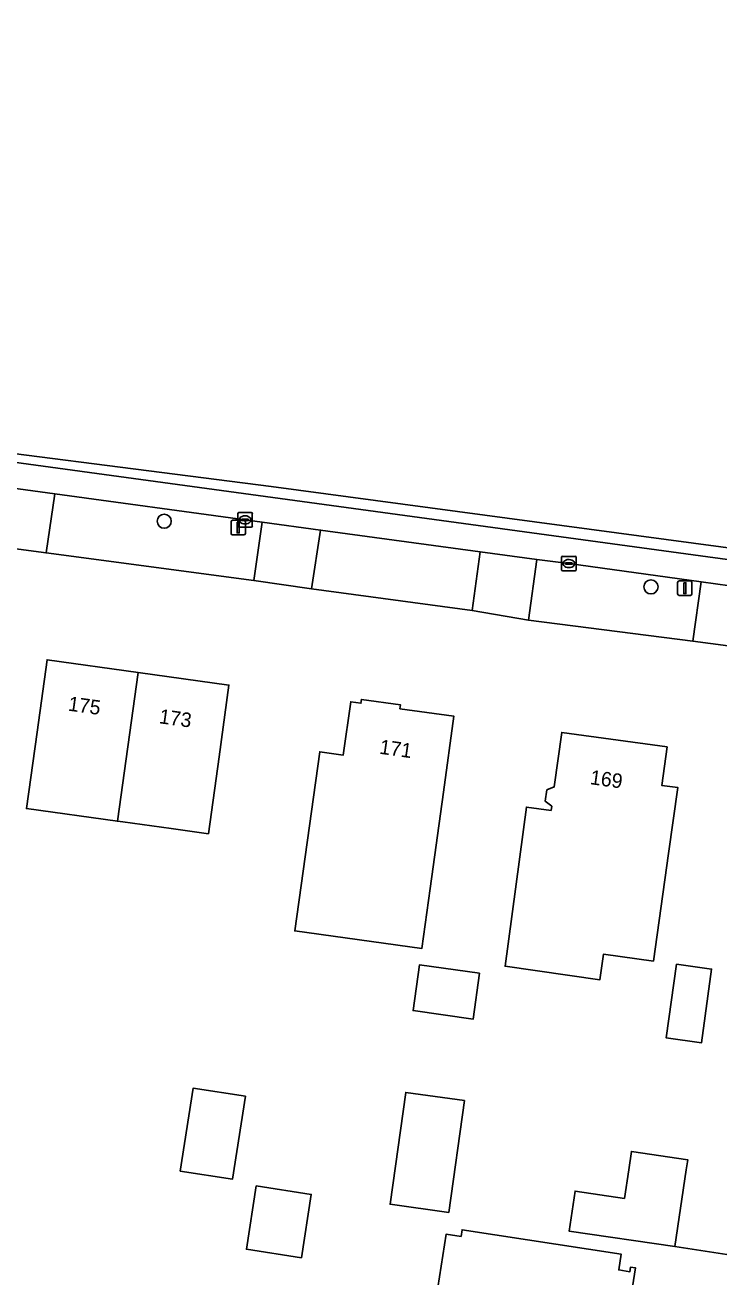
# Model space of a CAD drawing. Extents: x 161483 to 162250, y 379484 to 380833.
# Drawn here: x 161897.6 to 161945.6, y 380742.6 to 380829.1 of the extents above; entities that cross this region are included whole.
import ezdxf

# ---------------------------------------------------------------- set-up
doc = ezdxf.new("R2010")
doc.units = 0
for name, color, linetype in [('IMGEO_Boom', 7, 'Continuous'), ('IMGEO_Erf', 7, 'Continuous'), ('IMGEO_Fietspad_open', 7, 'Continuous'), ('IMGEO_Kolk', 7, 'Continuous'), ('IMGEO_Lichtmast', 7, 'Continuous'), ('IMGEO_Muur', 7, 'Continuous'), ('IMGEO_Pand', 7, 'Continuous'), ('IMGEO_Pand_nummerreeks', 7, 'Continuous'), ('IMGEO_Rijbaan_lokaal_gesloten', 7, 'Continuous'), ('IMGEO_Voetpad_open', 7, 'Continuous')]:
    doc.layers.add(name, color=color, linetype=linetype)

msp = doc.modelspace()

# ---------------------------------------------------------------- linework, layer by layer
at = {"layer": 'IMGEO_Boom'}
for centre in [(161907.254, 380794.81), (161940.876, 380790.272)]:
    msp.add_circle(centre, 0.489, dxfattribs=at)
at = {"layer": 'IMGEO_Erf'}
for points in [[(161947.776, 380785.993), (161943.772, 380786.523), (161932.427, 380787.968), (161928.533, 380788.644), (161917.439, 380790.128), (161913.448, 380790.714), (161899.09, 380792.619), (161891.993, 380793.568), (161881.272, 380795.068), (161877.324, 380795.561), (161866.903, 380796.964), (161862.786, 380797.518), (161845.524, 380799.914), (161837.657, 380800.986)], [(161926.166, 380741.862), (161926.734, 380745.548), (161927.761, 380745.389), (161927.832, 380745.853), (161938.822, 380744.157), (161938.654, 380743.069), (161939.424, 380742.95), (161939.474, 380743.275), (161939.8, 380743.225), (161938.78, 380736.645)]]:
    msp.add_lwpolyline(points, dxfattribs=at)
for points in [[(161911.042, 380778.536), (161910.304, 380773.211), (161907.742, 380773.567), (161904.397, 380774.032), (161904.022, 380774.075), (161897.735, 380774.947), (161898.469, 380780.238), (161899.161, 380785.231), (161905.445, 380784.36), (161911.729, 380783.488)], [(161916.273, 380766.5), (161917.998, 380778.875), (161919.624, 380778.649), (161920.136, 380782.334), (161920.845, 380782.235), (161920.881, 380782.495), (161923.58, 380782.12), (161923.542, 380781.847), (161927.268, 380781.33), (161926.551, 380776.089), (161925.626, 380769.427), (161925.049, 380765.276)], [(161932.274, 380775.058), (161933.984, 380774.825), (161934.024, 380775.116), (161933.578, 380775.464), (161933.686, 380776.244), (161934.198, 380776.452), (161934.72, 380780.218), (161941.991, 380779.21), (161941.62, 380776.554), (161942.727, 380776.412), (161942.091, 380771.854), (161941.053, 380764.418), (161937.601, 380764.9), (161937.349, 380763.122), (161930.801, 380764.057)], [(161929.043, 380763.574), (161928.602, 380760.409), (161924.445, 380760.989), (161924.886, 380764.154)], [(161942.64, 380764.197), (161945.061, 380763.861), (161944.378, 380758.777), (161941.931, 380759.11)], [(161912.863, 380755.076), (161911.972, 380749.338), (161908.367, 380749.898), (161909.258, 380755.636)], [(161927.99, 380754.774), (161926.912, 380747.045), (161922.861, 380747.61), (161923.939, 380755.339)], [(161939.527, 380751.264), (161943.416, 380750.69), (161943.314, 380750), (161942.53, 380744.682), (161935.226, 380745.759), (161935.633, 380748.522), (161939.048, 380748.017), (161939.341, 380750)], [(161917.415, 380748.294), (161916.735, 380743.917), (161912.936, 380744.507), (161913.616, 380748.884)]]:
    msp.add_lwpolyline(points, close=True, dxfattribs=at)
at = {"layer": 'IMGEO_Fietspad_open'}
for points in [[(161944.816, 380792.342), (161887.22, 380800.191), (161845.075, 380805.921), (161833.402, 380807.634), (161828.42, 380808.407)], [(161838.216, 380805.069), (161846.078, 380803.976), (161847.071, 380803.724), (161851.906, 380803.091), (161863.408, 380801.636), (161867.481, 380801.087), (161868.7, 380800.923), (161877.899, 380799.667), (161881.879, 380799.119), (161886.971, 380798.442), (161889.046, 380798.166), (161892.587, 380797.666), (161899.699, 380796.708), (161912.838, 380794.902), (161914.017, 380794.744), (161918.055, 380794.201), (161929.077, 380792.694), (161932.993, 380792.169), (161935.206, 380791.883), (161944.345, 380790.629), (161948.316, 380790.073)], [(162082, 380773.982), (162090.414, 380772.833), (162103.563, 380771.053), (162105.995, 380770.702), (162108.893, 380770.206), (162109.295, 380770.138), (162113.227, 380769.38), (162121.37, 380767.728), (162122.685, 380767.488), (162126.662, 380766.696), (162139.522, 380764.129), (162139.7, 380764.105), (162139.976, 380766.161), (162138.618, 380766.344), (162118.907, 380770.062), (162108.19, 380772.217), (162093.056, 380774.264), (162086.162, 380775.288), (162081.643, 380775.785), (162056.903, 380777.191), (162056.354, 380777.224), (162034.971, 380780.165), (161944.816, 380792.342)]]:
    msp.add_lwpolyline(points, dxfattribs=at)
at = {"layer": 'IMGEO_Kolk'}
for p, q in [((161912.341, 380794.475), (161912.341, 380795.327)), ((161912.416, 380795.401), (161913.268, 380795.401)), ((161912.829, 380795.181), (161912.854, 380795.181)), ((161913.342, 380795.327), (161913.342, 380794.475)), ((161913.268, 380794.401), (161912.416, 380794.401)), ((161912.6, 380794.895), (161912.6, 380794.907)), ((161913.038, 380794.858), (161912.64, 380794.858)), ((161912.643, 380794.944), (161913.041, 380794.944)), ((161912.852, 380794.621), (161912.827, 380794.621)), ((161913.084, 380794.907), (161913.084, 380794.895)), ((161934.708, 380791.456), (161934.708, 380792.308)), ((161934.783, 380792.382), (161935.635, 380792.382)), ((161934.967, 380791.876), (161934.967, 380791.888)), ((161935.405, 380791.839), (161935.007, 380791.839)), ((161935.01, 380791.925), (161935.408, 380791.925)), ((161935.196, 380792.162), (161935.221, 380792.162)), ((161935.451, 380791.888), (161935.451, 380791.876)), ((161935.709, 380792.308), (161935.709, 380791.456)), ((161935.635, 380791.382), (161934.783, 380791.382)), ((161935.219, 380791.602), (161935.194, 380791.602))]:
    msp.add_line(p, q, dxfattribs=at)
for points in [[(161912.341, 380794.475), (161912.341, 380795.327)], [(161912.416, 380795.401), (161913.268, 380795.401)], [(161913.342, 380795.327), (161913.342, 380794.475)], [(161913.268, 380794.401), (161912.416, 380794.401)], [(161934.708, 380791.456), (161934.708, 380792.308)], [(161934.783, 380792.382), (161935.635, 380792.382)], [(161935.709, 380792.308), (161935.709, 380791.456)], [(161935.635, 380791.382), (161934.783, 380791.382)]]:
    msp.add_lwpolyline(points, dxfattribs=at)
for centre, radius, start, end in [((161912.418, 380795.325), 0.0765, 91.55205, 178.44795), ((161912.418, 380795.325), 0.0765, 91.55205, 178.44795), ((161913.266, 380795.325), 0.0765, 1.55205, 88.44795), ((161913.266, 380795.325), 0.0765, 1.55205, 88.44795), ((161912.418, 380794.477), 0.0765, 181.55205, 268.44795), ((161912.418, 380794.477), 0.0765, 181.55205, 268.44795), ((161912.64, 380794.904), 0.0403, 85.87752, 175.75265), ((161912.637, 380794.894), 0.0366, 178.93798, 274.71019), ((161913.041, 380794.901), 0.043, 264.86636, 352.45326), ((161913.045, 380794.906), 0.0386, 1.73085, 96.63898), ((161913.266, 380794.477), 0.0765, 271.55205, 358.44795), ((161913.266, 380794.477), 0.0765, 271.55205, 358.44795), ((161934.785, 380792.306), 0.0765, 91.55205, 178.44795), ((161934.785, 380792.306), 0.0765, 91.55205, 178.44795), ((161935.007, 380791.885), 0.0403, 85.87752, 175.75265), ((161935.004, 380791.875), 0.0366, 178.93798, 274.71019), ((161935.408, 380791.882), 0.043, 264.86636, 352.45326), ((161935.412, 380791.887), 0.0386, 1.73085, 96.63898), ((161935.633, 380792.306), 0.0765, 1.55205, 88.44795), ((161935.633, 380792.306), 0.0765, 1.55205, 88.44795), ((161934.785, 380791.458), 0.0765, 181.55205, 268.44795), ((161934.785, 380791.458), 0.0765, 181.55205, 268.44795), ((161935.633, 380791.458), 0.0765, 271.55205, 358.44795), ((161935.633, 380791.458), 0.0765, 271.55205, 358.44795)]:
    msp.add_arc(centre, radius, start, end, dxfattribs=at)
for centre, major_axis, ratio, start_param, end_param in [((161912.828, 380794.901), (-0.387, 0.002), 0.722429, 4.712389, 7.853982), ((161912.853, 380794.901), (-0.39, 0.002), 0.717154, 1.570796, 4.712389), ((161935.195, 380791.882), (-0.387, 0.002), 0.722429, 4.712389, 7.853982), ((161935.22, 380791.882), (-0.39, 0.002), 0.717154, 1.570796, 4.712389)]:
    msp.add_ellipse(centre, major_axis=major_axis, ratio=ratio, start_param=start_param, end_param=end_param, dxfattribs=at)
at = {"layer": 'IMGEO_Lichtmast'}
for p, q in [((161911.873, 380793.97), (161911.873, 380794.77)), ((161911.873, 380794.77), (161911.873, 380793.97)), ((161911.973, 380794.87), (161912.763, 380794.87)), ((161912.763, 380794.87), (161911.973, 380794.87)), ((161912.863, 380794.77), (161912.863, 380793.97)), ((161912.863, 380793.97), (161912.863, 380794.77)), ((161912.763, 380793.87), (161911.973, 380793.87)), ((161911.973, 380793.87), (161912.763, 380793.87)), ((161942.72, 380789.783), (161942.72, 380790.583)), ((161942.72, 380790.583), (161942.72, 380789.783)), ((161942.82, 380790.683), (161943.61, 380790.683)), ((161943.61, 380790.683), (161942.82, 380790.683)), ((161943.71, 380790.583), (161943.71, 380789.783)), ((161943.71, 380789.783), (161943.71, 380790.583)), ((161943.61, 380789.683), (161942.82, 380789.683)), ((161942.82, 380789.683), (161943.61, 380789.683))]:
    msp.add_line(p, q, dxfattribs=at)
for points in [[(161912.293, 380794.745), (161912.443, 380794.745), (161912.443, 380793.995), (161912.293, 380793.995), (161912.293, 380794.745)], [(161943.14, 380790.558), (161943.29, 380790.558), (161943.29, 380789.808), (161943.14, 380789.808), (161943.14, 380790.558)]]:
    msp.add_lwpolyline(points, dxfattribs=at)
for centre, start, end in [((161911.973, 380794.77), 90, 180), ((161911.973, 380794.77), 90, 180), ((161912.763, 380794.77), 0, 90), ((161912.763, 380794.77), 360, 90), ((161911.973, 380793.97), 180, 270), ((161911.973, 380793.97), 180, 270), ((161912.763, 380793.97), 270, 0), ((161912.763, 380793.97), 270, 0), ((161942.82, 380790.583), 90, 180), ((161942.82, 380790.583), 90, 180), ((161943.61, 380790.583), 0, 90), ((161943.61, 380790.583), 360, 90), ((161942.82, 380789.783), 180, 270), ((161942.82, 380789.783), 180, 270), ((161943.61, 380789.783), 270, 0), ((161943.61, 380789.783), 270, 0)]:
    msp.add_arc(centre, 0.1, start, end, dxfattribs=at)
at = {"layer": 'IMGEO_Muur'}
msp.add_lwpolyline([(161942.53, 380744.682), (161955.105, 380742.751)], dxfattribs=at)
at = {"layer": 'IMGEO_Pand'}
for points in [[(161904.022, 380774.075), (161905.445, 380784.36), (161899.161, 380785.231), (161898.469, 380780.238), (161897.735, 380774.947)], [(161911.042, 380778.536), (161911.729, 380783.488), (161905.445, 380784.36), (161904.022, 380774.075), (161904.397, 380774.032), (161907.742, 380773.567), (161910.304, 380773.211)], [(161919.624, 380778.649), (161917.998, 380778.875), (161916.273, 380766.5), (161925.049, 380765.276), (161925.626, 380769.427), (161926.551, 380776.089), (161927.268, 380781.33), (161923.542, 380781.847), (161923.58, 380782.12), (161920.881, 380782.495), (161920.845, 380782.235), (161920.136, 380782.334)], [(161941.053, 380764.418), (161942.091, 380771.854), (161942.727, 380776.412), (161941.62, 380776.554), (161941.991, 380779.21), (161934.72, 380780.218), (161934.198, 380776.452), (161933.686, 380776.244), (161933.578, 380775.464), (161934.024, 380775.116), (161933.984, 380774.825), (161932.274, 380775.058), (161930.801, 380764.057), (161937.349, 380763.122), (161937.601, 380764.9)], [(161929.043, 380763.574), (161924.886, 380764.154), (161924.445, 380760.989), (161928.602, 380760.409)], [(161942.64, 380764.197), (161941.931, 380759.11), (161944.378, 380758.777), (161945.061, 380763.861)], [(161912.863, 380755.076), (161909.258, 380755.636), (161908.367, 380749.898), (161911.972, 380749.338)], [(161922.861, 380747.61), (161926.912, 380747.045), (161927.99, 380754.774), (161923.939, 380755.339)], [(161942.53, 380744.682), (161943.314, 380750), (161943.416, 380750.69), (161939.527, 380751.264), (161939.341, 380750), (161939.048, 380748.017), (161935.633, 380748.522), (161935.226, 380745.759)], [(161912.936, 380744.507), (161916.735, 380743.917), (161917.415, 380748.294), (161913.616, 380748.884)], [(161939.8, 380743.225), (161939.474, 380743.275), (161939.424, 380742.95), (161938.654, 380743.069), (161938.822, 380744.157), (161927.832, 380745.853), (161927.761, 380745.389), (161926.734, 380745.548), (161926.166, 380741.862), (161926.369, 380741.832), (161926.334, 380741.606), (161925.971, 380739.249), (161922.983, 380739.709), (161922.06, 380733.719), (161925.038, 380733.264), (161931.563, 380732.267), (161932.437, 380737.949), (161938.504, 380737.02), (161938.454, 380736.695), (161938.78, 380736.645)]]:
    msp.add_lwpolyline(points, close=True, dxfattribs=at)
at = {"layer": 'IMGEO_Rijbaan_lokaal_gesloten'}
for points in [[(162235.883, 380761.117), (162225.793, 380762.232), (162195.841, 380761.556), (162155.522, 380766.113), (162152.312, 380766.476), (162100.246, 380775.712), (162094.38, 380775.785), (162063.3, 380779.137), (162022.247, 380782.773), (161914.65, 380797.204), (161859.959, 380804.218), (161826.791, 380811.355), (161807.579, 380816.265), (161765.369, 380823.138), (161719.379, 380829.094), (161719.203, 380827.684), (161722.585, 380827.174), (161725.837, 380826.617)], [(161833.402, 380807.634), (161845.075, 380805.921), (161887.22, 380800.191), (161944.816, 380792.342), (162034.971, 380780.165), (162056.354, 380777.224), (162056.903, 380777.191), (162081.643, 380775.785), (162086.162, 380775.288), (162093.056, 380774.264), (162108.19, 380772.217), (162118.907, 380770.062), (162138.618, 380766.344), (162139.976, 380766.161), (162155.313, 380764.1), (162157.657, 380763.785), (162175.214, 380761.306), (162198.829, 380757.994), (162207.5, 380757.078), (162216.737, 380756.638)]]:
    msp.add_lwpolyline(points, dxfattribs=at)
at = {"layer": 'IMGEO_Voetpad_open'}
for points in [[(161899.09, 380792.619), (161899.699, 380796.708), (161892.587, 380797.666), (161891.993, 380793.568)], [(161913.448, 380790.714), (161914.017, 380794.744), (161912.838, 380794.902), (161899.699, 380796.708), (161899.09, 380792.619)], [(161917.439, 380790.128), (161918.055, 380794.201), (161914.017, 380794.744), (161913.448, 380790.714)], [(161928.533, 380788.644), (161929.077, 380792.694), (161918.055, 380794.201), (161917.439, 380790.128)], [(161932.427, 380787.968), (161932.993, 380792.169), (161929.077, 380792.694), (161928.533, 380788.644)], [(161943.772, 380786.523), (161944.345, 380790.629), (161935.206, 380791.883), (161932.993, 380792.169), (161932.427, 380787.968)], [(161952.821, 380789.486), (161948.316, 380790.073), (161944.345, 380790.629), (161943.772, 380786.523), (161947.776, 380785.993), (161952.345, 380785.378)]]:
    msp.add_lwpolyline(points, close=True, dxfattribs=at)

# ---------------------------------------------------------------- texts
at = {"layer": 'IMGEO_Pand_nummerreeks'}
for s, rotation, p in [('175', 352.10427, (161900.578, 380781.724)), ('173', 352.10464, (161906.862, 380780.852)), ('171', 351.9869, (161922.083, 380778.747)), ('169', 352.10722, (161936.63, 380776.642))]:
    msp.add_text(s, height=1, rotation=rotation, dxfattribs=at).set_placement(p)

doc.saveas('drawing.dxf')
